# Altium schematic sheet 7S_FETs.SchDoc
size 431 x 279 mm; Date: Not shown in title block; ApprovedBy: Not shown in title block; CheckedBy: Not shown in title block; Author: Not shown in title block; CompanyName: Not shown in title block; Engineer: Not shown in title block; Organization: Not shown in title block; Address1: Not shown in title block; Address2: Not shown in title block; Address3: Not shown in title block; Address4: Not shown in title block; DocumentNumber: 3; Revision: Use project parameter SCH_Rev; SheetNumber: 3; SheetTotal: 5; PageSetup: Record=PageOptions¦CenterHorizontal=True¦CenterVertical=True¦PrintScale=0.64¦XCorrection=1.00¦YCorrection=1.00¦PrintKind=0¦BorderSize=5000000¦LeftOffset=0¦BottomOffset=0¦Orientation=2¦PaperLength=1000¦PaperWidth=1000¦Scale=100¦PaperSource=15¦PrintQuality=600¦MediaType=1¦DitherType=10¦PrintScaleMode=1¦PaperKind=Letter
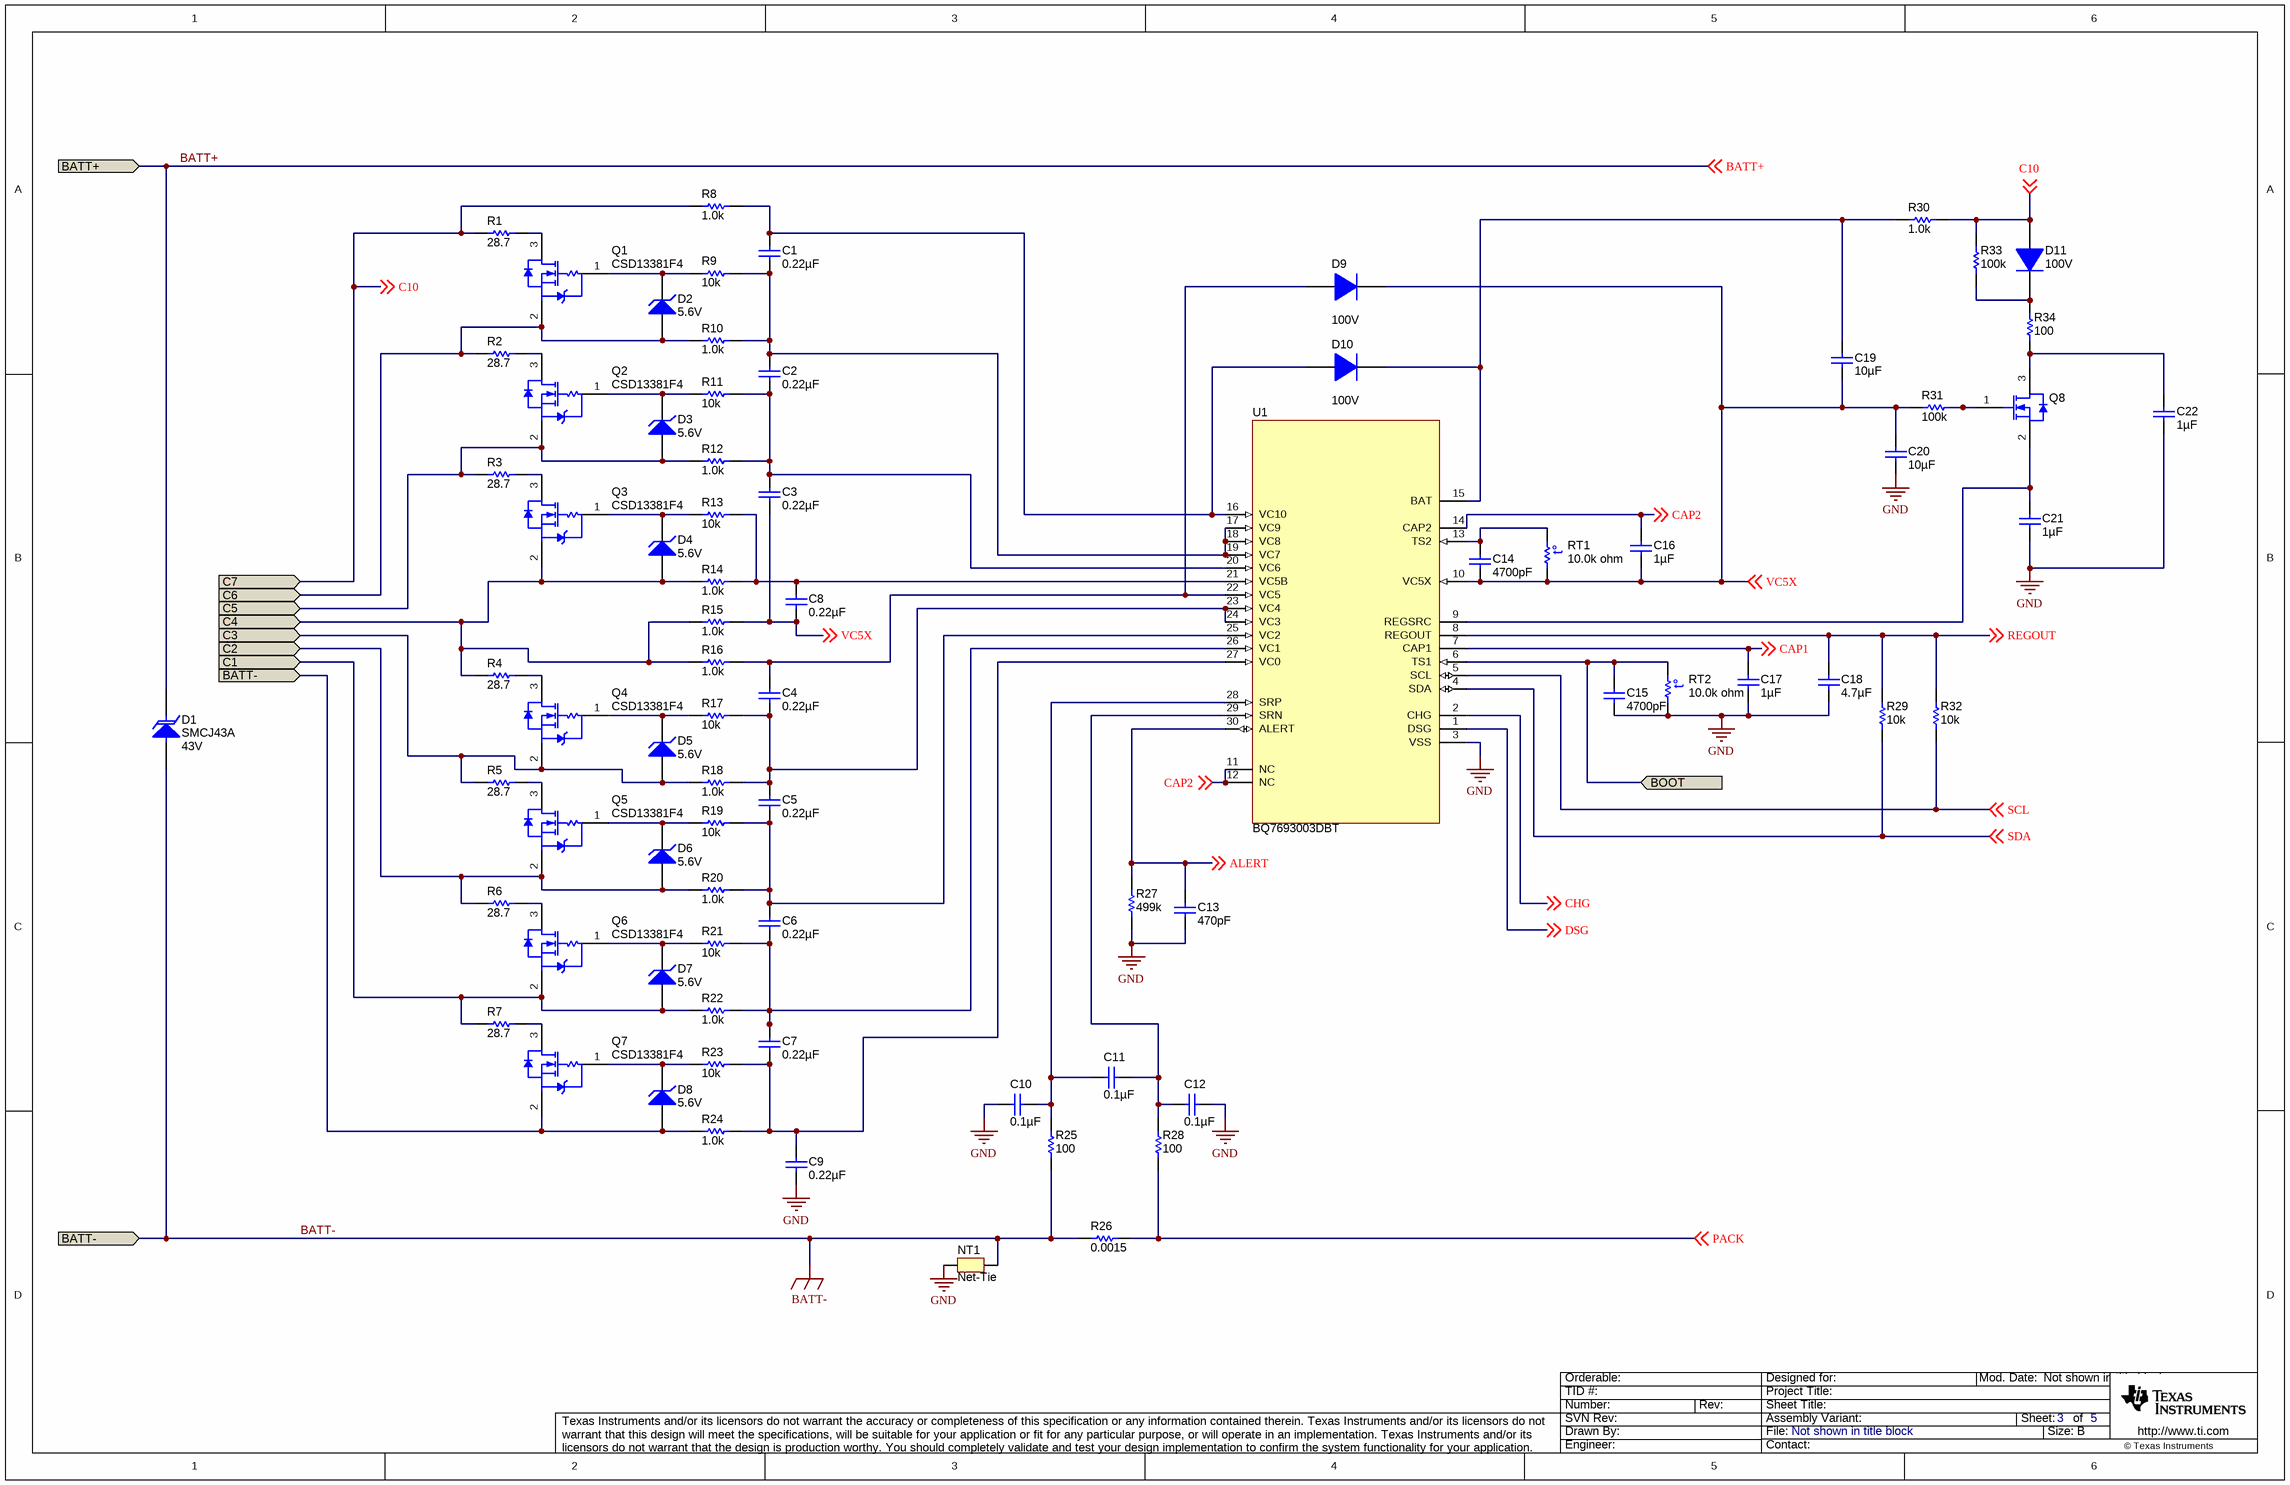
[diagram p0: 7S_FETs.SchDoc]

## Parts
C1  ValueDisplayed: 0.22µF  [0603_095]  (hidden comment: 885012206048)
C2  ValueDisplayed: 0.22µF  [0603_095]  (hidden comment: 885012206048)
C3  ValueDisplayed: 0.22µF  [0603_095]  (hidden comment: 885012206048)
C4  ValueDisplayed: 0.22µF  [0603_095]  (hidden comment: 885012206048)
C5  ValueDisplayed: 0.22µF  [0603_095]  (hidden comment: 885012206048)
C6  ValueDisplayed: 0.22µF  [0603_095]  (hidden comment: 885012206048)
C7  ValueDisplayed: 0.22µF  [0603_095]  (hidden comment: 885012206048)
C8  ValueDisplayed: 0.22µF  [0603_095]  (hidden comment: 885012206048)
C9  ValueDisplayed: 0.22µF  [0603_095]  (hidden comment: 885012206048)
C10  ValueDisplayed: 0.1µF  [0603_095]  (hidden comment: 885012206095)
C11  ValueDisplayed: 0.1µF  [0603_095]  (hidden comment: 885012206095)
C12  ValueDisplayed: 0.1µF  [0603_095]  (hidden comment: 885012206095)
C13  ValueDisplayed: 470pF  [0603_095]  (hidden comment: 885012206081)
C14  ValueDisplayed: 4700pF  [0603_095]  (hidden comment: 885012206087)
C15  ValueDisplayed: 4700pF  [0603_095]  (hidden comment: 885012206087)
C16  ValueDisplayed: 1µF  [0603_095]  (hidden comment: 885012206052)
C17  ValueDisplayed: 1µF  [0603_095]  (hidden comment: 885012206052)
C18  ValueDisplayed: 4.7µF  [0805_145]  (hidden comment: 885012207025)
C19  ValueDisplayed: 10µF  [1210]  (hidden comment: GRM32ER7YA106KA12L)
C20  ValueDisplayed: 10µF  [1210]  (hidden comment: GRM32ER7YA106KA12L)
C21  ValueDisplayed: 1µF  [0805]  (hidden comment: GRM21BR71H105KA12L)
C22  ValueDisplayed: 1µF  [0805_HV]  (hidden comment: GRM21BR71H105KA12L)
D1  SMCJ43A  value 43V  [SMC_265]
D2  value 5.6V  [sod-323]  (hidden comment: MMSZ5232BS-7-F)
D3  value 5.6V  [sod-323]  (hidden comment: MMSZ5232BS-7-F)
D4  value 5.6V  [sod-323]  (hidden comment: MMSZ5232BS-7-F)
D5  value 5.6V  [sod-323]  (hidden comment: MMSZ5232BS-7-F)
D6  value 5.6V  [sod-323]  (hidden comment: MMSZ5232BS-7-F)
D7  value 5.6V  [sod-323]  (hidden comment: MMSZ5232BS-7-F)
D8  value 5.6V  [sod-323]  (hidden comment: MMSZ5232BS-7-F)
D9  value 100V  [SOD-123]  (hidden comment: 1N4148W-7-F)
D10  value 100V  [SOD-123]  (hidden comment: 1N4148W-7-F)
D11  value 100V  [SOD-123]  (hidden comment: 1N4148W-7-F)
NT1  Net-Tie  [Net-Tie_10mil]  (net tie, no BOM)
Q1  CSD13381F4  [YJC0003A]
Q2  CSD13381F4  [YJC0003A]
Q3  CSD13381F4  [YJC0003A]
Q4  CSD13381F4  [YJC0003A]
Q5  CSD13381F4  [YJC0003A]
Q6  CSD13381F4  [YJC0003A]
Q7  CSD13381F4  [YJC0003A]
Q8  2N7002ET1G  [SOT-23]  (value not drawn)
R1  ValueDisplayed: 28.7  [2010]  (hidden comment: CRCW201028R7FKEF)
R2  ValueDisplayed: 28.7  [2010]  (hidden comment: CRCW201028R7FKEF)
R3  ValueDisplayed: 28.7  [2010]  (hidden comment: CRCW201028R7FKEF)
R4  ValueDisplayed: 28.7  [2010]  (hidden comment: CRCW201028R7FKEF)
R5  ValueDisplayed: 28.7  [2010]  (hidden comment: CRCW201028R7FKEF)
R6  ValueDisplayed: 28.7  [2010]  (hidden comment: CRCW201028R7FKEF)
R7  ValueDisplayed: 28.7  [2010]  (hidden comment: CRCW201028R7FKEF)
R8  ValueDisplayed: 1.0k  [0603]  (hidden comment: CRCW06031K00JNEA)
R9  ValueDisplayed: 10k  [0603]  (hidden comment: CRCW060310K0JNEA)
R10  ValueDisplayed: 1.0k  [0603]  (hidden comment: CRCW06031K00JNEA)
R11  ValueDisplayed: 10k  [0603]  (hidden comment: CRCW060310K0JNEA)
R12  ValueDisplayed: 1.0k  [0603]  (hidden comment: CRCW06031K00JNEA)
R13  ValueDisplayed: 10k  [0603]  (hidden comment: CRCW060310K0JNEA)
R14  ValueDisplayed: 1.0k  [0603]  (hidden comment: CRCW06031K00JNEA)
R15  ValueDisplayed: 1.0k  [0603]  (hidden comment: CRCW06031K00JNEA)
R16  ValueDisplayed: 1.0k  [0603]  (hidden comment: CRCW06031K00JNEA)
R17  ValueDisplayed: 10k  [0603]  (hidden comment: CRCW060310K0JNEA)
R18  ValueDisplayed: 1.0k  [0603]  (hidden comment: CRCW06031K00JNEA)
R19  ValueDisplayed: 10k  [0603]  (hidden comment: CRCW060310K0JNEA)
R20  ValueDisplayed: 1.0k  [0603]  (hidden comment: CRCW06031K00JNEA)
R21  ValueDisplayed: 10k  [0603]  (hidden comment: CRCW060310K0JNEA)
R22  ValueDisplayed: 1.0k  [0603]  (hidden comment: CRCW06031K00JNEA)
R23  ValueDisplayed: 10k  [0603]  (hidden comment: CRCW060310K0JNEA)
R24  ValueDisplayed: 1.0k  [0603]  (hidden comment: CRCW06031K00JNEA)
R25  value 100  [0805_HV]  (hidden comment: CRCW0805100RFKEA)
R26  ValueDisplayed: 0.0015  [ULRB22512_085]  (hidden comment: ULRB22512R0015FLFSLT)
R27  ValueDisplayed: 499k  [0603]  (hidden comment: CRCW0603499KFKEA)
R28  value 100  [0805_HV]  (hidden comment: CRCW0805100RFKEA)
R29  ValueDisplayed: 10k  [0603]  (hidden comment: CRCW060310K0JNEA)
R30  ValueDisplayed: 1.0k  [0603]  (hidden comment: CRCW06031K00JNEA)
R31  value 100k  [0805_HV]  (hidden comment: CRCW0805100KFKEA)
R32  ValueDisplayed: 10k  [0603]  (hidden comment: CRCW060310K0JNEA)
R33  value 100k  [0805_HV]  (hidden comment: CRCW0805100KFKEA)
R34  value 100  [0805_HV]  (hidden comment: CRCW0805100RFKEA)
RT1  value 10.0k ohm  [Thermistor_103AT-2]  (hidden comment: 103AT-2)
RT2  value 10.0k ohm  [Thermistor_103AT-2]  (hidden comment: 103AT-2)
U1  BQ7693003DBT  [DBT0030A_N]

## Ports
BATT+, BATT-, BOOT, C1, C2, C3, C4, C5, C6, C7

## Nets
BATT-: D1.2(A) D8.2(A) NT1.2 Q7.2(S) R24.1 R25.1 R26.1 ; port BATT-
GND: C9.2 C10.2 C12.1 C13.2 C15.2 C17.2 C18.2 C20.2 C21.2 C22.2 NT1.1 R27.1 RT2.1 U1.3(VSS)
ALERT: C13.1 R27.2 U1.30(ALERT) ; off-sheet ALERT
BATT+: D1.1(K) ; off-sheet BATT+, port BATT+
BOOT: C15.1 RT2.2 U1.6(TS1) ; port BOOT
C1: D7.2(A) Q6.2(S) R7.1 R22.1 ; port C1
C2: D6.2(A) Q5.2(S) R6.1 R20.1 ; port C2
C3: D5.2(A) Q4.2(S) R5.1 R18.1 ; port C3
C4: D4.2(A) Q3.2(S) R4.1 R14.1 R15.1 R16.1 ; port C4
C5: D3.2(A) Q2.2(S) R3.1 R12.1 ; port C5
C6: D2.2(A) Q1.2(S) R2.1 R10.1 ; port C6
C10: D11.2(A) R1.1 R8.1 R30.2 R33.1 ; off-sheet C10, port C7
CAP1: C17.1 U1.7(CAP1) ; off-sheet CAP1
CAP2: C16.1 U1.11(NC) U1.12(NC) U1.14(CAP2) ; off-sheet CAP2
CHG: U1.2(CHG) ; off-sheet CHG
DSG: U1.1(DSG) ; off-sheet DSG
PACK: R26.2 R28.1 ; off-sheet PACK
REGOUT: C18.1 R29.2 R32.1 U1.8(REGOUT) ; off-sheet REGOUT
SCL: R32.2 U1.5(SCL) ; off-sheet SCL
SDA: R29.1 U1.4(SDA) ; off-sheet SDA
VC5X: C3.2 C8.2 C14.2 C16.2 C19.2 C20.1 D9.1(K) R15.2 R31.1 RT1.1 U1.10(VC5X) ; off-sheet VC5X
NetC1_1: C1.1 D10.2(A) R8.2 U1.16(VC10)
NetC1_2: C1.2 C2.1 R9.2 R10.2 U1.17(VC9) U1.18(VC8) U1.19(VC7)
NetC2_2: C2.2 C3.1 R11.2 R12.2 U1.20(VC6)
NetC4_1: C4.1 D9.2(A) R16.2 U1.22(VC5)
NetC4_2: C4.2 C5.1 R17.2 R18.2 U1.23(VC4) U1.24(VC3)
NetC5_2: C5.2 C6.1 R19.2 R20.2 U1.25(VC2)
NetC6_2: C6.2 C7.1 R21.2 R22.2 U1.26(VC1)
NetC7_2: C7.2 C9.1 R23.2 R24.2 U1.27(VC0)
NetC8_1: C8.1 R13.2 R14.2 U1.21(VC5B)
NetC10_1: C10.1 C11.2 R25.2 U1.28(SRP)
NetC11_1: C11.1 C12.2 R28.2 U1.29(SRN)
NetC14_1: C14.1 RT1.2 U1.13(TS2)
NetC19_1: C19.1 D10.1(K) R30.1 U1.15(BAT)
NetC21_1: C21.1 Q8.2(S) U1.9(REGSRC)
NetC22_1: C22.1 Q8.3(D) R34.2
NetD2_1: D2.1(K) Q1.1(G) R9.1
NetD3_1: D3.1(K) Q2.1(G) R11.1
NetD4_1: D4.1(K) Q3.1(G) R13.1
NetD5_1: D5.1(K) Q4.1(G) R17.1
NetD6_1: D6.1(K) Q5.1(G) R19.1
NetD7_1: D7.1(K) Q6.1(G) R21.1
NetD8_1: D8.1(K) Q7.1(G) R23.1
NetD11_1: D11.1(K) R33.2 R34.1
NetQ1_3: Q1.3(D) R1.2
NetQ2_3: Q2.3(D) R2.2
NetQ3_3: Q3.3(D) R3.2
NetQ4_3: Q4.3(D) R4.2
NetQ5_3: Q5.3(D) R5.2
NetQ6_3: Q6.3(D) R6.2
NetQ7_3: Q7.3(D) R7.2
NetQ8_1: Q8.1(G) R31.2

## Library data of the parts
C1-C9 = 885012206048: CAP, CERM, 0.22 µF, 16 V, +/- 10%, X7R, 0603_095; Manufacturer: Wurth Elektronik; Polarized: N; CompType: Capacitor; Value: 0.22uF; U/M: EA; Cap_F: 0.00000022; Tolerance_%: 10; Value1: Unknown; VDC_V: 16; Value2: 16V; TaMin_C: -55; TaMax_C: 125; Cap_Case: 0603
C10-C12 = 885012206095: CAP, CERM, 0.1 µF, 50 V, +/- 10%, X7R, 0603_095; Manufacturer: Wurth Elektronik; Polarized: N; CompType: Capacitor; Value: 0.1uF; U/M: EA; Cap_F: 0.0000001; Tolerance_%: 10; Value1: Unknown; VDC_V: 50; Value2: 50V; TaMin_C: -55; TaMax_C: 125; Cap_Case: 0603
C13 = 885012206081: CAP, CERM, 470 pF, 50 V, +/- 10%, X7R, 0603_095; Manufacturer: Wurth Elektronik; Polarized: N; CompType: Capacitor; Value: 470pF; U/M: EA; Cap_F: 0.00000000047; Tolerance_%: 10; Value1: Unknown; VDC_V: 50; Value2: 50V; TaMin_C: -55; TaMax_C: 125; Cap_Case: 0603
C14 C15 = 885012206087: CAP, CERM, 4700 pF, 50 V, +/- 10%, X7R, 0603_095; Manufacturer: Wurth Elektronik; Polarized: N; CompType: Capacitor; Value: 4700pF; U/M: EA; Cap_F: 0.0000000047; Tolerance_%: 10; Value1: Unknown; VDC_V: 50; Value2: 50V; TaMin_C: -55; TaMax_C: 125; Cap_Case: 0603
C16 C17 = 885012206052: CAP, CERM, 1 µF, 16 V, +/- 10%, X7R, 0603_095; Manufacturer: Wurth Elektronik; Polarized: N; CompType: Capacitor; Value: 1uF; U/M: EA; Cap_F: 0.000001; Tolerance_%: 10; Value1: Unknown; VDC_V: 16; Value2: 16V; TaMin_C: -55; TaMax_C: 125; Cap_Case: 0603
C18 = 885012207025: CAP, CERM, 4.7 µF, 10 V, +/- 10%, X7R, 0805; Manufacturer: Wurth Elektronik; Polarized: N; CompType: Capacitor; Value: 4.7uF; U/M: EA; Cap_F: 0.0000047; Tolerance_%: 10; Value1: Unknown; Value2: 10V; TaMin_C: -55; TaMax_C: 125; Cap_Case: 0805
C19 C20 = GRM32ER7YA106KA12L: CAP, CERM, 10uF, 35V, +/-10%, X7R, 1210; Manufacturer: MuRata; Polarized: N; CompType: Capacitor; U/M: EA; Cap_F: 0.00001; Tolerance_%: 10; Value1: Unknown; VDC_V: 35; TaMin_C: -55; TaMax_C: 125
C21 = GRM21BR71H105KA12L: CAP, CERM, 1 µF, 50 V, +/- 10%, X7R, 0805; Manufacturer: MuRata; Polarized: N; CompType: Capacitor; Value: 1uF; U/M: EA; Cap_F: 0.000001; Tolerance_%: 10; Value1: Unknown; VDC_V: 50; Value2: 50V; TaMin_C: -55; TaMax_C: 125
C22 = GRM21BR71H105KA12L: CAP, CERM, 1 µF, 50 V, +/- 10%, X7R, 0805; Manufacturer: MuRata; Polarized: N; CompType: Capacitor; Value: 1uF; U/M: EA; Cap_F: 0.000001; Tolerance_%: 10; Value1: Unknown; VDC_V: 50; Value2: 50V; TaMin_C: -55; TaMax_C: 125; Cap_Case: 0805
D1 = SMCJ43A: Diode, TVS, Uni, 43 V, 69.4 Vc, SMC; Manufacturer: Fairchild Semiconductor; U/M: EA; Vr_V: 43; Value1: W; SizeAreaWB_mm2: 78.5757; SizeArea_mm2: 46.8857; SizeX_mm: 7.94; SizeY_mm: 5.905; SizeZ_mm: 2.62; AEC Category: Q101
D2-D8 = MMSZ5232BS-7-F: Diode, Zener, 5.6V, 200mW, SOD-323; Manufacturer: Diodes Inc.; U/M: EA; Power_W: 0.2; Vz_V: 5.6; Value1: 0.2W; RJA_CperW: 350
D9 D10 = 1N4148W-7-F: Diode, Ultrafast, 100V, 0.15A, SOD-123; Manufacturer: Diodes Inc.; U/M: EA; Vf_V: 1.25; Value2: 1.25V; Io_A: 0.15; Vr_V: 100; TJmax_C: 150
D11 = 1N4148W-7-F: Diode, Ultrafast, 100V, 0.15A, SOD-123; Manufacturer: Diodes Inc.; U/M: EA; Vf_V: 1.25; Io_A: 0.15; Vr_V: 100; Value2: 1.25V; TJmax_C: 150
NT1 = Net-Tie: Single point connection between nets.; SymbolCreator: codlsc
Q1-Q7 = CSD13381F4: MOSFET, N/P-CH, 12 V, 2.1 A, 1.0x0.35x0.6mm; Manufacturer: Texas Instruments; Alternate Manufacturer: None; SymbolCreator: a0411947; U/M: EA; ChType: N; Value: 12V; VdsMax_V: 12; Value1: 0.14 ohm; Rdson45_ohm: 0.14; Value2: 1.06 nC; QgTyp_nC: 1.06; Vgs_V: 8; IdsMax_A: 2.1
Q8 = 2N7002ET1G: MOSFET, N-CH, 60 V, 0.26 A, SOT-23; Manufacturer: ON Semiconductor; Alternate Manufacturer: None; U/M: EA; ChType: N; Value: 60V; VdsMax_V: 60; Value1: 3 ohm; Rdson45_ohm: 3; Value2: 0.81 nC; QgTyp_nC: 0.81; Vgs_V: 20; IdsMax_A: 0.26
R1-R7 = CRCW201028R7FKEF: RES, 28.7, 1%, 0.75 W, 2010; Manufacturer: Vishay-Dale; CompType: Resistor; Value: 28.7; Value_Code: 28R7; Tolerance_%: 1; Power_W: 0.75; Value2: 0.75W; VDC_V: 400; TempCo: 100 ppm/C; EIA_Code: E96; U/M: EA
R8 R10 R12 R14-R16 R18 R20 R22 R24 R30 = CRCW06031K00JNEA: RES, 1.0 k, 5%, 0.1 W, 0603; Manufacturer: Vishay-Dale; CompType: Resistor; Value: 1.0k; Res_ohm: 1000; Value_Code: 1k00; Tolerance_%: 5; Power_W: 0.1; Value2: 0.1W; VDC_V: 75; TempCo: 200 ppm/C; EIA_Code: E24; U/M: EA
R9 R11 R13 R17 R19 R21 R23 R29 R32 = CRCW060310K0JNEA: RES, 10 k, 5%, 0.1 W, 0603; Manufacturer: Vishay-Dale; CompType: Resistor; Value: 10k; Res_ohm: 10000; Value_Code: 10k0; Tolerance_%: 5; Power_W: 0.1; Value2: 0.1W; VDC_V: 75; TempCo: 200 ppm/C; EIA_Code: E24; U/M: EA
R25 R28 R34 = CRCW0805100RFKEA: RES, 100 ohm, 1%, 0.125W, 0805; Manufacturer: Vishay-Dale; CompType: Resistor; Value_Code: 100R; Tolerance_%: 1; Power_W: 0.125; VDC_V: 150; TempCo: 100 ppm/C; EIA_Code: E96; U/M: EA
R26 = ULRB22512R0015FLFSLT: RES, 0.0015, 1%, 2 W, AEC-Q200 Grade 0, 2512; Manufacturer: TT Electronics/IRC; CompType: Resistor; Value: 0.0015; Value_Code: 1L500; Tolerance_%: 1; Power_W: 2; Value2: 2W; TempCo: 50 ppm/C; U/M: EA; AEC Category: Q200; AEC Qualified: Y; AEC Grade: 0
R27 = CRCW0603499KFKEA: RES, 499 k, 1%, 0.1 W, 0603; Manufacturer: Vishay-Dale; CompType: Resistor; Value: 499k; Res_ohm: 499000; Tolerance_%: 1; Power_W: 0.1; Value2: 0.1W; VDC_V: 75; TempCo: 100 ppm/C; EIA_Code: E96; U/M: EA
R31 R33 = CRCW0805100KFKEA: RES, 100k ohm, 1%, 0.125W, 0805; Manufacturer: Vishay-Dale; CompType: Resistor; Res_ohm: 100000; Tolerance_%: 1; Power_W: 0.125; VDC_V: 150; TempCo: 100 ppm/C; EIA_Code: E96; U/M: EA
RT1 RT2 = 103at-2: Thermistor NTC, 10.0k ohm, 1%, Disc, 5x8.4 mm; Manufacturer: SEMITEC Corporation; Tolerance_%: 1; Power_W: 0.01; TaMin_C: -50; TaMax_C: 110; U/M: EA
U1 = BQ7693003DBT: Battery Monitor for Lithium-Ion and Phosphate Battery Packs, DBT0030A; Manufacturer: Texas Instruments; SymbolCreator: a0799628; CompType: IC; U/M: EA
